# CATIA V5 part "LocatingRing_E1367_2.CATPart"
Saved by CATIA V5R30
Part number: Stredici_krouzek_levy
Nomenclature: E1367/125/90X20
Description: MEUSBURGER
Property "Material": "1.0503"
Publications: "DrillHole", "Base", "TapHole"
Bounding box of the stored display mesh (mm): x -62.5 to 62.5, y -62.5 to 62.5, z -8 to 12
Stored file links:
  E:\Bakalarka\Model\Forma_v7\LocatingRing_E1367_2.CATPart
  E:\dev\MoldDesign\intel_a\startup\components\MoldCatalog\LocatingRing\Meusburger\LocatingRing_E1367\TableE1367.txt
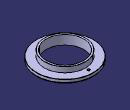
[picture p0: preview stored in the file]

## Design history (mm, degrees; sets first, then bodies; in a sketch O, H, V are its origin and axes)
Parameters
  Ref = "E1367/125/90X20" {design table}
  ShD = 125 mm {design table}
  L = 20 mm {design table}
  L3 = 8 mm {design table}
  D1 = 90 mm {design table}
  D2 = 82 mm {design table}
  D3 = 125 mm {design table}
  L4 = 2 mm {design table}
  R = 3 mm {design table}
  F = 0.3 mm {design table}
  F1 = 0.5 mm {design table}
  W1 = 30 deg {design table}
  L1 = 11.8 mm {design table}
  D4 = 104 mm {design table}
  M = 5 mm {design table}
  D5 = 5.5 mm {design table}
  D6 = 9.5 mm {design table}
  T6 = 6 mm {design table}
  k_l5 = 12 mm {design table}
  k_dkern = 4.13 mm {design table}
  k_lkern = 14 mm {design table}
  Version = 2 {design table}
  Pitch = 0.8 mm {design table}
  Mat = "1.0503" {design table}
  HeatTreat = "" {design table}
  SupplierRef = "Meusburger 2017"
  BmpRef = "F_MldLocatingRing_D1_D3_L"
  DrillHole_Length = 225 mm
  D = 90 mm {= D1}
Set1 "BaseBody"
  Point1 "Base": (0, 0, 0)
  Plane1: type Offset, RefPlane xy-plane, Offset 225 {= DrillHole_Length}, reversed
  Plane2: type Offset, RefPlane xy-plane, Offset -8
Body1 (main body)
  Sketch1 "Sketch.1" on yz-plane, origin (0, 0, 0), H (0, 1, 0), V (0, 0, 1)
    point P1 (41, -8)
    line L1 (41, -8) -> (62.5, -8)
    line L2 (62.5, -8) -> (62.5, 0)
    line L3 (62.5, 0) -> (45, 0)
    line L4 (45, 0) -> (45, 12)
    axis line L5 (0, -8) -> (0, 12)
    point P6 (0, -8)
    point P7 (0, 12)
    point P8 (41, -8)
    line L6 (41, -8) -> (41, 12)
    line L7 (41, 12) -> (45, 12)
    distance L4 L5 = 45 {= D1 /2}
    distance L2 L5 = 62.5 {= D3/2}
    distance L6 L5 = 41 {= D2 /2}
    distance L1 L7 = 20 {= L}
    length L2 = 8 {= L3}
    horizontal: L1 H, L3 H, L7 H
    vertical: L2 V, L4 V, L6 V
    coincidence: P6 V, L5 V, L3 H, P8 P1, P6 L1, P7 L7
  Shaft1: profile Sketch1, axis Sketch1.L5, angle 360
  Sketch2 "Sketch.2" on Plane2, origin (-12.4424, -33.1984, -8), H (1, 0, 0), V (0, -1, 0)
    point P1 (12.4424, -85.1984)
    construction circle A1 centre (12.4424, -33.1984) radius 52
    reference projected point E1 (12.4424, -33.1984) from Point1
    reference intersected line E2 through (12.4424, 0) direction (0, 1) from yz-plane
    radius A1 = 52 {= D4 /2}
    coincidence: P1 A1, E2 P1
    concentricity: A1 E1
  Hole1: placed by Sketch2, at (0, 52, -8) direction (0, 0, 1), diameter 5.5 {= D5}, through (limit type 3), counterbore diameter 9.5 {= D6}, counterbore depth 6 {= T6}
  Mirror1: of Hole1, about zx-plane
  Chamfer1: length 2 {= L4}, angle 30 {= W1}, on edge [face of Shaft1 from Sketch1.L1 | face of Shaft1 from Sketch1.L2]
  Chamfer2: length 0.5 {= F1}, angle 45, on edge [face of Shaft1 from Sketch1.L2 | face of Shaft1 from Sketch1.L3]
  Chamfer3: length 0.3 {= F}, angle 45, on edge [face of Shaft1 from Sketch1.L4 | face of Shaft1 from Sketch1.L7]
  Chamfer4: length 0.5 {= F1}, angle 45, on edge [face of Shaft1 from Sketch1.L3 | face of Shaft1 from Sketch1.L4], deactivated
Body2 "DrillHole"
  Sketch3 "Sketch.3" on Plane1, origin (0, 0, -225), H (1, 0, 0), V (0, 1, 0)
    point P1 (0, 0)
    reference projected point E1 (0, 0) from Point1
    coincidence: E1 P1
  Hole2: placed by Sketch3, at (0, 0, -225) direction (0, 0, 1), diameter 90 {= D1}, depth 237 {= Plane1.Offset +k_l5}
Body3 "TapHole"
  Sketch4 "Sketch.4" on xy-plane, origin (3.608, -3.608, 0), H (1, 0, 0), V (0, 1, 0)
    point P1 (-3.608, 55.608)
    construction circle A1 centre (-3.608, 3.608) radius 52
    reference projected circle E1 centre (-3.608, 3.608) radius 44.7 from edge [face of Chamfer3 | face of Shaft1 from Sketch1.L7]
    reference intersected line E2 through (-3.608, 0) direction (0, 1) from yz-plane
    radius A1 = 52 {= D4/2}
    concentricity: A1 E1
    coincidence: P1 A1, E2 P1
  Hole3: placed by Sketch4, at (0, 52, 0) direction (0, 0, 1), diameter 4.13 {= k_dkern}, depth 14 {= Hole3.ThreadingDepth}, V-bottom angle 120, threaded, thread diameter 5 {= M}, thread depth 14, pitch 0.8 {= Pitch}
  Mirror2: of the body so far, about zx-plane
Relations
  design table "TableE1367", configuration 15, drives Ref, ShD, L, L3, D1, D2, D3, L4, R, F, F1, W1, L1, D4, M, D5, D6, T6, k_l5, k_dkern, k_lkern, Version, Pitch, Mat, HeatTreat
  rule "D1-D3_definition":
    if ShD>D
    {
    	Chamfer2.Activity = true
    	Chamfer4.Activity = false
    }
    if D>ShD or D==ShD
    {
    	Chamfer2.Activity = false
    	Chamfer4.Activity = true
    }
  rule "Holes_position":
    if D4 >ShD
    	Plane2.Offset =0mm
    if D4<ShD or ShD==D
    	Plane2.Offset =-L3
  rule "Taphole_Activity":
    If Version == 1
    {
    	Hole3.ThreadingDepth = (L-L3) + k_lkern
    }
    If Version == 2
    {
    	Hole3.ThreadingDepth = k_lkern
    }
